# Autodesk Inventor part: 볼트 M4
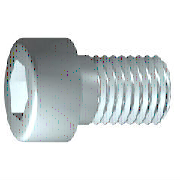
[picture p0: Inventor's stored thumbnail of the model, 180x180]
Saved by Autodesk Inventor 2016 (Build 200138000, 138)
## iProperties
IsCustomPart: 0
Created: 2012-02
Part Number: 볼트 M4
Material: 스테인리스강
Description: 6각 소켓 머리 캡 나사
Document SubType Name: Modeling
Standard: ISO 4762
Designer: mduedu
Standard Revision: Fourth edition 2004-03-01
Standards Organization: ISO
Language: ko-KR
Size Designation: M4 x 12
Categories: <MemberInstance><Categories><Category DisplayName="조임쇠" InternalName="e4da775c-781d-43d5-af7c-5136215cf5a6" Mnemonic="FSTN"><Category DisplayName="볼트" InternalN
Density: 8.08 g/cm^3
Mass: 2.29719 g
Surface Area: 3.30853 cm^2
Volume: 0.284306 cm^3
Appearance: 반광택
Author: mduedu
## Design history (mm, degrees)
sketch "스케치1"
  geometry: L1 (-1, 0)-(12, 0); L2 (12, 0)-(12, 2); L3 (12, 2)-(1.75, 2); L4 (1.75, 2)-(1.32, 2); L5 (1.32, 2)-(0, 2); L6 (0, 2)-(0, 3.5); L7 (0, 3.5)-(-4, 3.5); L8 (-4, 3.5)-(-4, 1.732); L9 (-4, 1.732)-(-2, 1.732); L10 (-2, 1.732)-(-1, 0); L11 (-7.2, 0)-(15.2, 0) reference; L12 (0, -0.7)-(0, 4.2) reference; L13 (1.75, 2)-(0, 2)
  constraints: 22 end point, 6 parallel, 2 collinear, 2 perpendicular, 1 horizontal, 1 point on line
  dimensions: "d1" = 10.25 distance from line of L3.end L2 (= GEL); "d2" = 0.42952 distance of L4.end L3.end (computed from GAL); "d3" = 4 distance between parallel lines of L8 L6 (= KOH); "d4" = 2 distance of L8.end L9.end (= INTI); "d5" = 60 deg angle of L10 L1; "d6" = 4 diameter of L3 L1 (= GD); "d7" = 4 diameter of L5 L1 (= BDM); "d8" = 3.4641 diameter of L9 L1 (= 1.1547 x SW); "d9" = 7 diameter of L7 L1 (= KOD); "d26" = 12 distance between parallel lines of L12 L2 (= NLG)
revolve "본체" sketch "스케치1" stored, may be unused: angle "d10" = 90 deg
sketch "스케치2"
  geometry: L1 (0, -4.9)-(0, 4.9) reference; L2 (-4.9, 0)-(4.9, 0) reference; L3 (1.732, 0)-(0.866, -1.5); L4 (0.866, -1.5)-(-0.866, -1.5); L5 (-0.866, -1.5)-(-1.732, 0); L6 (-1.732, 0)-(-0.866, 1.5); L7 (-0.866, 1.5)-(0.866, 1.5); L8 (0.866, 1.5)-(1.732, 0); 2 further points
  constraints: 12 end point, 1 coincident, 1 horizontal alignment, 1 point on line, 12 other
extrude "슬롯" join sketch "스케치2" stored distance "d11" = 10; taper "d12" = 0 deg
workplane "Work Plane1"
fillet "Fillet2" dims "d30" = 0.1 (= R)
body "Solid1"
fillet "모깎기1" dims "d17" = 0.4 (= RR)
feature "스레드" dims "d13" = 10.25 (= GEL), "d14" = 0
chamfer "모따기1" distance "d15" = 0.42941 (= -0.5 x SPD + 0.5 x GD); stored, may be unused: second distance "d16" = 0.42941 (= GUL), angle "d27" = 45 deg
other parameters: "GD" = 4 [user parameter; used in 2 equation terms], "NLG" = 12 [user parameter; used in 1 equation term], "GEL" = 10.25 [user parameter; used in 2 equation terms], "KOD" = 7 [user parameter; used in 1 equation term], "KOH" = 4 [user parameter; used in 1 equation term], "INTI" = 2 [user parameter; used in 1 equation term], "GAL" = 0.42941 (= 0.61345 x PTC) [user parameter; used in 1 equation term], "GUL" = 0.42941 (= 0.61345 x PTC) [user parameter; used in 1 equation term], "BDM" = 4 (= NND) [user parameter; used in 1 equation term], "SW" = 3 [user parameter; used in 2 equation terms], "RR" = 0.4 [user parameter; used in 1 equation term], "SPD" = 3.14117 (= NND - 1.2269 x PTC) [user parameter; used in 1 equation term], "d19" = 0, "d28" = 0, "d29" = 0, "R" = 0.1 [user parameter; used in 1 equation term], "TOA" = 30 deg [user parameter], "GD1" = 3.14117 (= THREADDIA - 1.2269 x PTC) [user parameter], "THREADDIA" = 4 [user parameter; used in 1 equation term], "FAWI" = 45 deg [user parameter], "TPU" = 14.28571 (computed from PTC) [user parameter], "PTC" = 0.7 [user parameter; used in 5 equation terms], "NND" = 4 [user parameter; used in 2 equation terms], "E0" = 3.465 (= 1.155 x SW) [user parameter]
